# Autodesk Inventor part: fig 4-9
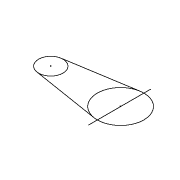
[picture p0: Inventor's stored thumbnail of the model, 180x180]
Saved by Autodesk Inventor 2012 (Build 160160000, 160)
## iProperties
Created: 2005-02
Part Number: fig 4-9
Document SubType Name: Modeling
Designer: CADCIM
Manufacturer: Standard
Standards Organization: Custom
Density: 1 g/cm^3
Material: Default
Author: CADCIM
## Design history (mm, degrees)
sketch "Sketch1"
  geometry: L1 (-28.496, 15.735)-(10.446, 21.986); L2 (-28.503, 2.004)-(10.432, -4.291); L3 (12.58, 26.117)-(12.58, -9.642); A1 r 6.954 centre (-27.393, 8.869) between (-28.496, 15.735) and (-28.503, 2.004); A2 r 13.308 centre (12.555, 8.846) between (10.446, 21.986) and (10.432, -4.291)
  constraints: 6 end point, 4 point on circle, 4 tangent, 2 centre point, 1 vertical, 1 other
